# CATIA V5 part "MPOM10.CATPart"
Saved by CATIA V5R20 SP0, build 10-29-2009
Part number: MPOM10
Definition: NONE
Nomenclature: MPOM10
Source: Unknown
Description: MPOM10
Bounding box of the stored display mesh (mm): x 0 to 12, y -5 to 5, z -5 to 5
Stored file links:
  C:\Users\Utente\Desktop\IO LAVORO\3D X SITO CF\X SITO\PLASTICA\CFMR\MPOM10.CATPart
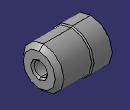
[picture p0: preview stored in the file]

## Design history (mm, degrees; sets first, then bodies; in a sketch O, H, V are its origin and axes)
Body1 "MPOM10" (main body)
  Solid1: solid without history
